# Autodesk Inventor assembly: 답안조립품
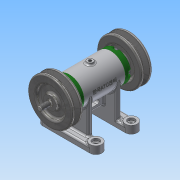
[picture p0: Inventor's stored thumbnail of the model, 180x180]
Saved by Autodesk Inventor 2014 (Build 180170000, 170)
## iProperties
Created: 2015-11
Part Number: 답안조립품
Document SubType Name: Assembly
Designer: 702
Author: 702
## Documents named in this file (9)
- C:\Users\702\Desktop\451109v1039\답안조립품.iam
- C:\Users\702\Desktop\451109v1039\1-본체.ipt
- C:\Users\702\Desktop\451109v1039\커버.ipt
- C:\Users\702\Desktop\451109v1039\오일 실 15 25 7.ipt
- C:\Users\702\Desktop\451109v1039\축.ipt
- C:\Users\702\Desktop\451109v1039\베어링 15 x 32 x 9.ipt
- C:\Users\702\Desktop\451109v1039\V벨트풀리.ipt
- C:\Users\702\Desktop\451109v1039\볼트 M4 x 12.ipt
- C:\Users\702\Desktop\451109v1039\키 3 x 3 x 12.ipt
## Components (13 placed, 4 different names)
1. 1-본체:1
2. KS B 2023 6002 - 15 x 32 x 9:1
3. KS B 2023 6002 - 15 x 32 x 9:2
4. V벨트풀리:1
5. V벨트풀리:2
6. ISO 4762 M4 x 12:1
7. ISO 4762 M4 x 12:3
8. ISO 4762 M4 x 12:4
9. ISO 4762 M4 x 12:5
10. ISO 4762 M4 x 12:2
11. ISO 4762 M4 x 12:6
12. ISO 4762 M4 x 12:7
13. ISO 4762 M4 x 12:8
